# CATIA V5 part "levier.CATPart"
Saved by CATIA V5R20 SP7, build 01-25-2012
Part number: levier
Bounding box of the stored display mesh (mm): x -98.739 to 98.739, y 597.391 to 802.609, z 0 to 20
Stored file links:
  U:\IAO\thinkmotion catia2\levier.CATPart
  U:\IAO\thinkmotion catia2\Ass_862_adubourgno.CATProduct
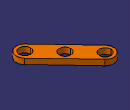
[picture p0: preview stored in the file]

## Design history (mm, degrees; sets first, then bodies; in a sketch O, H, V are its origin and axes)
Set1
  Plane1: linked copy from another document
  Point1 "B2": linked copy from another document
  Point2 "B": linked copy from another document
  Point3 "A": linked copy from another document
Body1 (main body)
  Sketch1 on Plane1, origin (0, 0, 0), H (1, 0, 0), V (0, 1, 0)
    axis line L1 (-68.75, 772.62) -> (68.75, 627.38)
    point P1 (-68.75, 772.62)
    point P2 (68.75, 627.38)
    reference projected point E1 (-68.75, 772.62) from Point1
    reference projected point E2 (68.75, 627.38) from Point2
    arc A1 centre (68.75, 627.38) radius 30 from (46.9642, 606.7552) to (90.5358, 648.0048) ccw
    point P3 (68.75, 627.38)
    reference projected point E3 (68.75, 627.38) from Point2
    arc A2 centre (-68.75, 772.62) radius 30 from (-46.9642, 793.2448) to (-90.5358, 751.9952) ccw
    point P4 (-68.75, 772.62)
    reference projected point E4 (-68.75, 772.62) from Point1
    line L2 (-46.9642, 793.2448) -> (90.5358, 648.0048)
    point P5 (90.5358, 648.0048)
    point P6 (98.75, 627.38)
    point P7 (-46.9642, 793.2448)
    line L3 (-90.5358, 751.9952) -> (46.9642, 606.7552)
    reference projected point E5 (-68.75, 772.62) from Point1
    reference projected point E6 (68.75, 627.38) from Point2
    circle A3 centre (0, 700) radius 20
    point P10 (0, 700)
    reference projected point E7 (0, 700) from Point3
    circle A4 centre (68.75, 627.38) radius 20
    point P11 (68.75, 627.38)
    reference projected point E8 (68.75, 627.38) from Point2
    circle A5 centre (-68.75, 772.62) radius 20
    point P12 (-68.75, 772.62)
    reference projected point E9 (-68.75, 772.62) from Point1
    distance E1 P1 = 0
    distance E2 P2 = 0
    radius A1 = 30
    distance E3 P3 = 0
    radius A2 = 30
    distance E4 P4 = 0
    distance L2 L1 = 30
    distance L3 L1 = 30
    distance E5 P7 = 30
    distance E6 P5 = 30
    radius A3 = 20
    distance E7 P10 = 0
    radius A4 = 20
    distance E8 P11 = 0
    radius A5 = 20
    distance E9 P12 = 0
  Pad1: profile Sketch1, direction (0, 0, 1), length 20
